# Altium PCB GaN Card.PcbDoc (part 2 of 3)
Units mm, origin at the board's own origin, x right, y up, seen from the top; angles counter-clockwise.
Board outline 50 x 40 mm, 6 copper layers (Top Layer, MidLayer1, MidLayer2, MidLayer3, MidLayer4, Bottom Layer), stack 1.981 mm thick; 88 components, 77 nets, 322 pads, 257 vias.
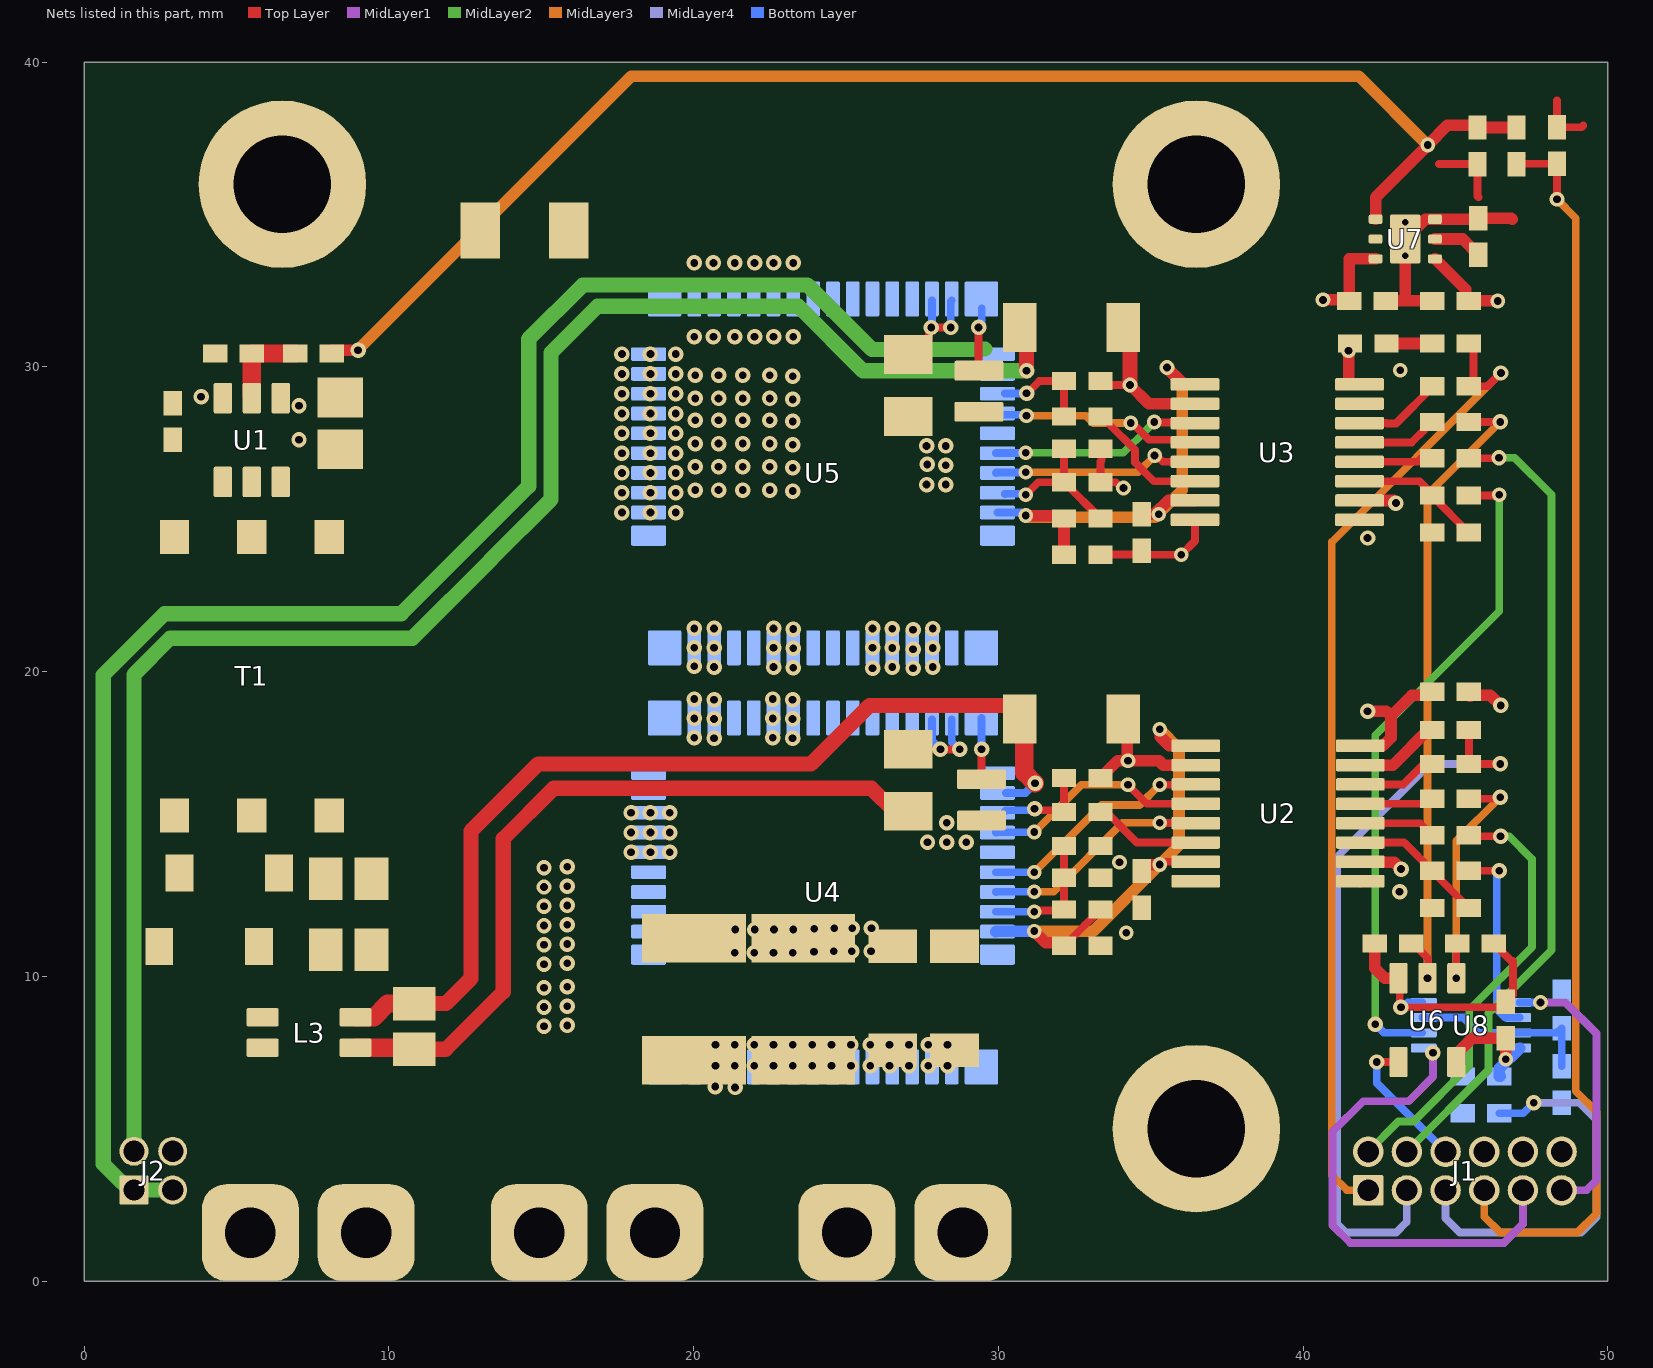
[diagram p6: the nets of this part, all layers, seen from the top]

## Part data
C1 C28 C30 C36 C37: library part CMP-0006356-2, "CAP, CERM, 0.1 uF, 50 V, +/- 10%, X7R, AEC-Q200 Grade 1, 0402", Cap_Case=0402, Manufacturer=MuRata, Supplier Part Number 1=490-10672-1-ND, TempCo=X7R, Tolerance_%=10%, Value1=Unknown, Value2=50V, ValueDisplayed=0.1uF
C2 C9 C10 C21: library part CMP-0076706-1, "CAP, CERM, 4.7 µF, 25 V,+/- 10%, X7R, AEC-Q200 Grade 1, 0805", Cap_Case=2x1.25x1.25mm, Manufacturer=TDK, Supplier Part Number 1=445-6967-1-ND, TempCo=X7R, Tolerance_%=10%, Value2=25V, ValueDisplayed=4.7µF
C3 C4 C13 C14 C16 C17: library part CMP-0006308-2, "CAP, CERM, 100 pF, 50 V, +/- 5%, C0G/NP0, AEC-Q200 Grade 1, 0402", Cap_Case=0402, Manufacturer=TDK, Supplier Part Number 1=445-5596-1-ND, TempCo=C0G/NP0, Tolerance_%=5%, Value1=Unknown, Value2=50V, ValueDisplayed=100pF
C5 C6 C7 C8 C39: library part CMP-0085818-1, "CAP, CERM, 1 µF, 10 V,+/- 10%, X7S, AEC-Q200 Grade 1, 0402", Cap_Case=0402, Manufacturer=MuRata, TempCo=X7S, Tolerance_%=10%, Value2=10V, ValueDisplayed=1µF
C11 C12: library part CMP-0008807-2, "CAP, CERM, 10 uF, 25 V, +/- 10%, X7S, AEC-Q200 Grade 1, 1206_190", Cap_Case=1206, Manufacturer=MuRata, Supplier Part Number 1=490-12661-1-ND, TempCo=X7S, Tolerance_%=10%, Value1=Unknown, Value2=25V, ValueDisplayed=10uF
C15 C19: library part CMP-0078265-1, "CAP, CERM, 0.22 µF, 16 V,+/- 10%, X7R, AEC-Q200 Grade 1, 0402", Cap_Case=0402, Manufacturer=MuRata, Supplier Part Number 1=490-10671-1-ND, TempCo=X7R, Tolerance_%=10%, Value2=16V, ValueDisplayed=0.22µF
C18 C20: library part CMP-0083622-1, "CAP, CERM, 2.2 µF, 25 V,+/- 10%, X7R, AEC-Q200 Grade 1, 0805", Cap_Case=0805, Manufacturer=MuRata, Supplier Part Number 1=490-4787-1-ND, TempCo=X7R, Tolerance_%=10%, Value2=25V, ValueDisplayed=2.2µF
C22 C23: library part CMP-0084048-1, "CAP, CERM, 0.022 µF, 1000 V,+/- 10%, X7R, AEC-Q200 Grade 1, 1206", Cap_Case=1206, Manufacturer=Kemet, TempCo=X7R, Tolerance_%=10%, Value2=1000V, ValueDisplayed=0.022µF
C24 C25: library part CMP-0009326-2, "CAP, CERM, 0.1 uF, 1000 V, +/- 10%, X7R, 1812", Cap_Case=1812, Manufacturer=Kemet, Supplier Part Number 1=399-6523-1-ND, TempCo=X7R, Tolerance_%=10%, Value1=Unknown, Value2=1000V, ValueDisplayed=0.1uF
C26 C27: library part CMP-0006356-1, "CAP, CERM, 0.1 uF, 50 V, +/- 10%, X7R, AEC-Q200 Grade 1, 0402", Cap_Case=0402, Manufacturer=MuRata, Supplier Part Number 1=490-10672-1-ND, TempCo=X7R, Tolerance_%=10%, Value1=Unknown, Value2=50V, ValueDisplayed=0.1uF
C32 C33 C34 C35: library part CMP-0860835-1, "CAP, CERM, 43 pF, 50 V,+/- 5%, C0G/NP0, AEC-Q200 Grade 1, 0402", Cap_Case=0402, Manufacturer=MuRata, TempCo=C0G/NP0, Tolerance_%=5%, Value2=50V, ValueDisplayed=43pF
C38: library part CMP-0006324-2, "CAP, CERM, 0.01 uF, 50 V, +/- 10%, X7R, AEC-Q200 Grade 1, 0402", Cap_Case=0402, Manufacturer=TDK, Supplier Part Number 1=445-6893-1-ND, TempCo=X7R, Tolerance_%=10%, Value1="0.333065 ohm", Value2=50V, ValueDisplayed=0.01uF
"CAUTION HOT SURFACE": library part CMP-0074837-1, "IEC 61010-1 Hot Surface Warning"
D2 D3: library part CMP-0028524-2, "Diode, Schottky, 20 V, 0.5 A, SOD-123", Manufacturer="ON Semiconductor", Value1=0.5A, Value2=0.385V
"DANGER HIGH VOLTAGE": library part CMP-0074835-1, "IEC 61010-1 High Voltage Warning"
J1: library part CMP-0120913-1, Current_A=3.4A, Digikey Part Number=SAM15643-ND, Manufacturer=Samtec, Mouser Part Number=200-FTSH10601LDRA, Operating Temperature Range="-55°C to +125°C"
J2: library part CMP-0120912-1, "Connector Unshrouded Header HDR 4 POS 1.27mm Solder RA Thru-Hole", Current_A=3.4A, Digikey Part Number=612-FTSH-102-01-L-D-RA-ND, Manufacturer=Samtec, Mouser Part Number=200-FTSH10201LDRA, Operating Temperature Range="-55°C to +125°C"
L1 L2: library part CMP-0089347-1, "4.7µH Unshielded Inductor 1.1A 426mOhm Max 0806 (2016 Metric)", Digikey Part Number=2037-SDEM20161T-4R7MSCT-ND, Manufacturer=Cyntec, Operating Temperature Range="-55°C to +125°C", Test Frequency=1MHz, Tolerance_%=20%
L3: library part CMP-0001686-1, "2 Line Common Mode Choke Surface Mount 1 kOhms @ 100 MHz 800mA DCR 150mOhm", Digikey Part Number=445-ACT32P-102-2P-TL01CT-ND, Impedance At Frequency="1000Ω @ 100MHz", Manufacturer=TDK, Mouser Part Number=810-ACT32P1022P-TL01, Operating Temperature Range="-55°C to +150°C", Tolerance_%=+30/-20%
LBL1: library part CMP-0003625-1, "Thermal Transfer Printable Labels, 0.650\" W x 0.200\" H - 10,000 per roll", Manufacturer=Brady, Supplier Part Number 1=97C5133
Logo1: library part CMP-0074844-1
Logo3: library part CMP-0074847-1, "FCC_disclaimer"
Logo4: library part CMP-0074769-1
R1 R2 R5 R6: library part CMP-0026404-2, "RES, 49.9, 1%, 0.063 W, AEC-Q200 Grade 0, 0402", Manufacturer=Vishay-Dale, Power_W=63mW, Supplier Part Number 1=541-49.9LCT-ND, TempCo="100 ppm/C", Tolerance_%=1%, Value2=0.063W, Value_Code=49R9, ValueDisplayed=49.9
R3 R4: library part CMP-0025951-3, "RES, 100, 1%, 0.063 W, AEC-Q200 Grade 0, 0402", Manufacturer=Vishay-Dale, Power_W=63mW, Supplier Part Number 1=541-100LCT-ND, TempCo="100 ppm/C", Tolerance_%=1%, Value2=0.063W, Value_Code=100R, ValueDisplayed=100
R7 R9: library part CMP-0025950-3, "RES, 100 k, 1%, 0.063 W, AEC-Q200 Grade 0, 0402", Manufacturer=Vishay-Dale, Power_W=63mW, Supplier Part Number 1=541-100KLCT-ND, TempCo="100 ppm/C", Tolerance_%=1%, Value2=0.063W, Value_Code=100k
R8 R14: library part CMP-0077124-1, "RES, 10.0 k, 0.1%, 0.1 W, AEC-Q200 Grade 0, 0402", Manufacturer=Vishay/Beyschlag, Power_W=100mW, Supplier Part Number 1=MCS0402-10.0K-MBCT-ND, TempCo="25 ppm/C", Tolerance_%=0.1%, Value2=0.1W, Value_Code=10k0, ValueDisplayed=10.0k
R10 R15: library part CMP-0026992-3, "RES, 0, 5%, 0.1 W, AEC-Q200 Grade 0, 0402", Manufacturer=Panasonic, Power_W=100mW, Supplier Part Number 1=P0.0JCT-ND, TempCo="600 ppm/C", Tolerance_%=5%, Value2=0.1W, Value_Code=0000, ValueDisplayed=0
R11 R12 R21 R22: library part CMP-0026902-3, "RES, 300, 5%, 0.063 W, AEC-Q200 Grade 0, 0402", Manufacturer=Vishay-Dale, Power_W=63mW, Supplier Part Number 1=541-300JCT-ND, TempCo="200 ppm/C", Tolerance_%=5%, Value2=0.063W, Value_Code=300R, ValueDisplayed=300
R13 R23: library part CMP-0026164-2, "RES, 20.0, 1%, 0.063 W, AEC-Q200 Grade 0, 0402", Manufacturer=Vishay-Dale, Power_W=63mW, Supplier Part Number 1=541-20.0LCT-ND, TempCo="100 ppm/C", Tolerance_%=1%, Value2=0.063W, Value_Code=20R0, ValueDisplayed=20.0
R16: library part CMP-0081856-1, "RES, 0, 0%, 0.2 W, AEC-Q200 Grade 0, 0402", Manufacturer=Vishay-Dale, Power_W=200mW, Supplier Part Number 1=541-0.0YBTR-ND, Tolerance_%=0%, Value2=0.2W, Value_Code=0
R25: library part CMP-0018573-3, "RES, 0, 5%, 0.25 W, AEC-Q200 Grade 0, 1206", Manufacturer=Vishay-Dale, Power_W=250mW, Supplier Part Number 1=541-0.0ECT-ND, TempCo="200 ppm/C", Tolerance_%=5%, Value2=0.25W, Value_Code=0000, ValueDisplayed=0
T1: library part CMP-0030718-1, "Transformer, 475uH, SMT", Manufacturer="Wurth Elektronik", Supplier Part Number 1=732-4458-1-ND, ValueDisplayed=475uH
TH1 TH2 TH3: library part CMP-0003719-1, "Testpoint", Manufacturer="Texas Instruments", PartNumber=TP_H0.45P0.75
TP1 TP2 TP3 TP4 TP5 TP6: library part CMP-0082316-1, "PCB Pin, 0.04\" DIA, Edge-Mount", Manufacturer=Mill-Max, Supplier Part Number 1=575-3621032150000
U1: library part CMP-0860735-1, "SN6505DQDBVRQ1, DBV0006A (SOT-23-6)", Alternate Manufacturer="Texas Instruments", Alternate PartNumber=SN6505DQDBVTQ1
U2 U3: library part CMP-0090469-1, "General Purpose Digital Isolator 2500Vrms 4 Channel 100Mbps 85kV/µs CMTI 16-SSOP (0.154\", 3.90mm Width)", Digikey Part Number=296-51207-1-ND, Manufacturer="Texas Instruments", Max Supply Voltage=5.5V, Min Supply Voltage=2.25V, Mouser Part Number=595-ISO7741FQDBQRQ1, Nominal Supply Current=1.5-18mA, Operating Temperature Range="-40°C to +125°C"
U4 U5: library part CMP-0094891-1, "650-V 30-mΩ GaN FET with Integrated Driver, Protection, and Temperature Reporting", Manufacturer="Texas Instruments", Max Supply Voltage=18V, Min Supply Voltage=7.5V, Nominal Supply Current=16mA, Operating Temperature Range="-40°C to +150°C", Output Voltage=520V
U6: library part CMP-0051573-2, "Automotive Catalog Single 2-Input Positive-AND Gate, DBV0005A (SOT-23-5)", F @ Nom Voltage(Max)(Mhz)=75, Generic Part Number=SN74AHC1G08-Q1, ICC @ Nom Voltage(Max)(mA)=0.01, Manufacturer="Texas Instruments", Operating Temperature Range="-40 to 125 C", Rating=Automotive, tpd @ Nom Voltage(Max)(ns)=12.3,7.9, Voltage(Nom)(V)=3.3,5
U7: library part CMP-0082417-1, "Low Noise, High-Bandwidth PSRR Low-Dropout 150mA Linear Regulator for Automotive Applications, DRV0006A (WSON-6)", Alternate Manufacturer="Texas Instruments", Operating Temperature Range="-40 to 125 C", Rating=Automotive
U8: library part CMP-0121233-1, "Automotive Dual Bilateral Analog Switch", Digikey Part Number=296-29056-1-ND, Manufacturer="Texas Instruments", Max Supply Voltage=5.5V, Min Supply Voltage=1.65V, Mouser Part Number=595-74LVC2G66QDCURQ1, Nominal Supply Current=1-15uA, On State Resistance=6Ω, Operating Temperature Range="-40°C to +125°C"

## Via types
v1: diameter 0.508, hole 0.254, Top Layer to Bottom Layer, tented both sides, 218 vias
v2: diameter 0.483, hole 0.254, Top Layer to Bottom Layer, tented both sides, 35 vias
v3: diameter 0.508, hole 0.254, Top Layer to Bottom Layer, 2 vias
v4: diameter 0.5, hole 0.2, Top Layer to Bottom Layer, 2 vias

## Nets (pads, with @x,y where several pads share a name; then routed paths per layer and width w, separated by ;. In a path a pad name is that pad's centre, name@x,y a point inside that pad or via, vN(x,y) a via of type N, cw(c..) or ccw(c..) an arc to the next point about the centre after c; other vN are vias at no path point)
3V3: C5.1 C6.1 C28.1 C36.1 C39.1 U2.10 U2.16 U3.10 U3.16 U6.5 U7.1 U8.8 | length 14.9
  Top Layer w0.381: v2(41.492,30.534) 41.502,30.534 41.502,29.444 41.517,29.429 U3.16@41.856,29.429 ; U3.10@41.856,25.619 42.968,25.619 v1(43.052,25.535) ; U2.16@41.881,17.567 42.623,17.567 42.889,17.834 42.889,18.545 ; v1(42.118,18.698) 42.737,18.698 42.889,18.545 ; U2.10@42.246,13.743 42.996,13.743 v1(43.22,13.519) ; C6.1@44.245,19.231 43.575,19.231 42.889,18.545 ; U7.1@44.332,33.55 45.333,32.549 45.333,32.169 v2(46.395,32.169) ; U6.5@45.033,7.188 45.033,7.444 45.553,7.963 C36.1@46.659,7.963 46.657,7.961 46.657,7.282 v2(46.655,7.28)
  Bottom Layer w0.381: C28.1@46.476,6.715 C28.1@46.445,6.715 46.445,6.975 U8.8@47.115,7.645
5V0: C1.1 C2.1 C37.1 J1.12 T1.5 U1.2 U7.6 | length 3.1
  Top Layer w0.381: v2(40.656,32.203) 41.484,32.203 C37.1@41.518,32.169 41.518,33.55 U7.6@42.382,33.55
  other v1: 7.046,27.615
5V_H: C8.1 C15.2 R15.1 U2.1 U2.7 U4.51 | length 17.5
  Top Layer w0.254: C15.2@32.155,11.103 32.26,11.103 32.839,11.683 32.842,11.683 R15.1@33.355,12.195 ; v2(35.295,13.669) 35.384,13.757 U2.7@36.481,13.757
  Top Layer w0.381: v2(31.18,11.484) 31.561,11.103 C15.2@32.155,11.103 ; C8.1@34.711,13.456 34.923,13.669 v2(35.295,13.669) ; v2(35.295,18.114) 35.314,18.094 35.314,17.858 35.605,17.567 U2.1@36.481,17.567
  MidLayer3 w0.381: v2(31.18,11.484) 33.11,11.484 v2(35.295,13.669) 35.93,14.304 35.93,17.479 v2(35.295,18.114)
  Bottom Layer w0.381: U4.51@29.921,11.469 29.928,11.477 31.173,11.477 v2(31.18,11.484)
5V_L: C7.2 C19.2 R10.1 U3.1 U3.7 U5.51 | length 16.3
  Top Layer w0.381: v2(30.901,25.124) 32.058,25.124 R10.1@32.155,25.027 C19.2@32.155,23.842 ; C7.2@34.711,25.165 v2@35.121,25.165 ; v2@35.263,25.193 v2(35.263,25.165) v2@35.121,25.165 ; v2(35.533,29.98) 36.084,29.429 U3.1@36.456,29.429 ; U3.7@36.456,25.619 35.575,25.619 v2@35.121,25.165
  MidLayer3 w0.381: v2(30.901,25.124) 30.928,25.124 30.979,25.073 35.143,25.073 v2@35.235,25.165 ; v2(35.263,25.165) v2@35.235,25.165 ; v2(35.533,29.98) 36.031,29.482 36.031,25.961 v2@35.235,25.165
  Bottom Layer w0.254: U5.51@29.971,25.223 v2@30.74,25.223
DGND: C1.2 C2.2 C3.2 C4.2 C5.2 C6.2 C26.2 C27.2 C28.2 C30.2 C32.2 C33.2 C34.2 C35.2 C36.2 C37.2 C38.2 C39.2 J1.8 J1.10 R8.1 R14.1 U1.4 U1.6 U2.9 U2.15 U3.9 U3.15 U6.3 U7.3 U7.7@43.357,34.2 U8.4 | length 25.7
  Top Layer w0.254: U6.3@43.133,9.648 43.175,9.607 43.175,9.029 v1(43.216,8.987) 46.486,8.987 46.659,9.16 C36.2@46.659,9.163 46.892,9.396 46.892,10.504 46.832,10.504 C34.2@46.258,11.078 ; C35.2@44.245,18.088 C35.2@44.302,18.088 ; 44.464,36.66 C27.2@45.727,36.66 45.727,35.603 45.757,35.573 ; 48.335,38.75 R14.1@48.335,37.87 49.141,37.87 49.2,37.929
  Top Layer w0.381: U2.9@41.881,13.122 U2.9@41.896,13.108 ; U2.15@41.881,16.932 42.952,16.932 44.108,18.088 C35.2@44.245,18.088 ; C33.2@42.352,11.078 42.352,10.267 42.681,9.938 U6.3@43.133,9.938 U6.3@43.133,9.648 ; C37.2@42.718,32.169 43.425,32.169 ; C5.2@42.742,30.772 C32.2@44.133,30.772 ; v1(43.17,12.778) v1@43.213,12.778 ; v4(43.357,33.65) 43.357,32.237 43.425,32.169 ; U7.7@43.357,34.2 44.007,34.85 U7.3@44.332,34.85 45.722,34.85 C38.2@45.757,34.884 46.834,34.884 46.868,34.85 ; C39.2@44.133,32.169 43.425,32.169 ; C6.2@45.48,19.196 45.515,19.231 46.148,19.231 v1(46.489,18.891)
  Bottom Layer w0.254: v1@43.297,8.905 43.297,8.999 43.442,9.145 U8.4@43.915,9.145
  other v1: 42.118,24.387
  other v2: 43.194,29.893
  other v3: 7.046,28.731 3.833,29.024
  other v4: 43.357,34.75
EN: C30.1 R16.2 U1.5 | length 2.8
  Top Layer w0.6: U1.5@5.496,29.078 C30.1@5.496,30.445 ; C30.1@5.501,30.446 R16.2@6.926,30.446
EN_DRV: J1.5 R3.1 R8.2 | length 13.9
  MidLayer4 w0.254: J1.5@44.679,2.975 44.679,2.061 45.149,1.591 49.124,1.591 49.632,2.098 49.632,5.3 49.077,5.854 v1(47.574,5.854)
  Bottom Layer w0.254: R8.2@46.445,5.505 47.225,5.505 v1(47.574,5.854) R3.1@48.489,5.854
"EN_ISO 12V": J1.7 R4.1 R14.2 | length 41.7
  Top Layer w0.254: R4.1@47.178,36.933 47.005,36.76 R4.1@47.005,36.66 47.015,36.67 R14.2@48.335,36.67 v2(48.335,35.505)
  MidLayer3 w0.254: J1.7@45.949,2.975 45.949,2.113 46.471,1.591 49.009,1.591 49.632,2.213 49.632,5.554 48.954,6.232 48.954,34.886 v2(48.335,35.505)
GaN_FAULT: J1.6 U6.4 | length 4.6
  Top Layer w0.254: v1(42.424,7.188) U6.4@43.133,7.188
  Bottom Layer w0.254: v1(42.424,7.188) 42.424,6.5 J1.6@44.679,4.245
HS_FAULT: C34.1 R22.2 U6.1 | length 8.7
  Top Layer w0.254: v1(45.033,9.938) 45.033,11.053 C34.1@45.058,11.078 ; R22.2@45.445,15.828 46.42,15.828 v1(46.471,15.878)
  MidLayer3 w0.254: v1(45.033,9.938) 45.033,14.441 v1(46.471,15.878)
HS_OC: C35.1 J1.3 R23.2 | length 24.4
  Top Layer w0.254: C35.1@45.445,18.088 R23.2@45.445,16.971 v1(46.471,16.971)
  MidLayer4 w0.254: J1.3@43.409,2.975 43.409,1.939 43.061,1.591 41.404,1.591 41.12,1.875 41.12,13.928 44.162,16.971 v1(46.471,16.971)
HS_PWM: J1.11 U8.5 | length 9
  MidLayer1 w0.254: v2(47.795,9.139) 48.615,9.139 49.632,8.122 49.632,3.304 49.303,2.975 J1.11@48.489,2.975
  MidLayer3 w0.254: v2@47.789,9.132 v2(47.795,9.139)
  Bottom Layer w0.254: U8.5@47.115,9.145 47.118,9.142 47.792,9.142 v2(47.795,9.139)
HS_PWM_IN: R2.1 U8.6 | length 6.4
  Top Layer w0.254: R2.1@45.445,13.465 v1(46.445,13.465)
  Bottom Layer w0.254: v1(46.445,13.465) 46.445,13.397 46.358,13.31 46.358,8.925 46.639,8.645 U8.6@47.115,8.645
HS_TEMP: J1.2 R21.2 | length 14.5
  Top Layer w0.254: R21.2@45.445,14.634 45.482,14.597 v1(46.486,14.597)
  MidLayer2 w0.254: J1.2@42.139,4.245 43.129,5.235 43.629,5.235 45.459,7.065 45.459,8.904 47.514,10.959 47.514,13.848 46.765,14.597 v1(46.486,14.597)
HVBUS: C22.1 C23.1 C24.1 C25.1 TP1.1 TP4.1 U4.2 U4.3 U4.4 U4.5 U4.6 U4.7 U4.8 U4.9 U4.10 U4.11 U4.12 U4.13 U4.14 U4.15
  other v1: 21.358,6.354 20.712,6.382 20.715,7.065 21.35,7.065 21.985,7.065 22.62,7.065 23.255,7.065 23.89,7.065 24.525,7.065 25.16,7.065 25.795,7.065 26.43,7.065 27.065,7.065 27.7,7.065 28.335,7.065 20.715,7.75 21.35,7.75 21.985,7.75 22.62,7.75 23.255,7.75 23.89,7.75 24.525,7.75 25.16,7.75 25.795,7.75 26.43,7.75 27.065,7.75 27.7,7.75 28.335,7.75
ISO_12V_H: C12.1 C21.1 L3.2 U4.44 | length 32.5
  Top Layer w0.5: C21.1@10.825,9.106 11.868,9.106 12.695,9.933 12.695,14.77 14.896,16.971 23.85,16.971 25.77,18.891 30.4,18.891 30.7,18.591 C12.1@30.7,18.45
  Top Layer w0.6: L3.2@8.901,8.656 9.506,8.656 9.956,9.106 C21.1@10.825,9.106 ; C12.1@30.7,18.45 30.855,18.295 30.855,16.686 v1(31.205,16.336)
  Bottom Layer w0.254: U4.44@30.252,16.019 30.889,16.019 v1(31.205,16.336)
ISO_12V_L: C11.1 J2.2 U5.44 | length 56.2
  Top Layer w0.5: C11.1@30.7,31.3 30.925,31.075 30.925,29.875 v1(30.926,29.874)
  MidLayer2 w0.5: J2.2@1.63,4.258 1.63,19.909 2.821,21.1 10.769,21.1 13.34,23.671 13.34,23.676 15.319,25.655 15.319,30.469 16.844,31.994 23.441,31.994 25.561,29.874 v1(30.926,29.874)
  Bottom Layer w0.254: U5.44@29.921,29.773 U5.44@29.971,29.773 30.757,29.773 30.857,29.874 v1(30.926,29.874)
ISO_-4V_L: J2.4
LS_FAULT: C33.1 R12.2 U6.2 | length 21.5
  Top Layer w0.254: C33.1@43.635,11.052 44.113,10.575 44.113,9.968 v1(44.083,9.938) ; R12.2@45.593,28.197 v1(46.471,28.197)
  MidLayer3 w0.254: v1(44.083,9.938) 44.083,25.81 v1(46.471,28.197)
LS_OC: C32.1 J1.1 R13.2 | length 32.6
  Top Layer w0.254: C32.1@45.333,30.772 45.593,30.513 45.593,29.366 46.069,29.366 46.069,29.376 v1(46.496,29.803)
  MidLayer3 w0.254: J1.1@42.139,2.975 41.446,2.975 40.946,3.475 40.946,24.253 v1(46.496,29.803)
LS_PWM: J1.9 U8.1 | length 15.8
  MidLayer1 w0.254: v1(44.265,7.495) 44.265,6.702 43.466,5.904 41.981,5.904 40.97,4.893 40.97,1.83 41.55,1.25 46.598,1.25 47.219,1.871 J1.9@47.219,2.975
LS_PWM_IN: R1.1 U8.2 | length 21.6
  Top Layer w0.254: R1.1@45.593,25.784 46.42,25.784 v2(46.445,25.81)
  MidLayer2 w0.254: v1(42.374,8.43) 42.374,17.909 46.445,21.981 v2(46.445,25.81)
  Bottom Layer w0.254: v1(42.374,8.43) 42.659,8.145 U8.2@43.915,8.145
LS_TEMP: J1.4 R11.2 | length 26.6
  Top Layer w0.254: R11.2@45.593,27.004 46.412,27.004 v1(46.433,27.024)
  MidLayer2 w0.254: J1.4@43.409,4.245 46.088,6.924 46.088,8.792 48.16,10.863 48.16,25.805 46.94,27.024 v1(46.433,27.024)
NC1: R25.2 TH1.1
NC2: TH2.1
NC3: TH3.1
NCT1: T1.2
NCU7: U7.5
NCU51: U4.1
NCU61: U5.1
NCU516: U4.16
NCU517: U4.17
NCU527: U4.27
NCU543: U4.43
NCU547: U4.47
NCU552: U4.52
NCU616: U5.16
NCU617: U5.17
NCU627: U5.27
NCU643: U5.43
NCU647: U5.47
NCU652: U5.52
NetC3_1: C3.1 R1.2 U3.11 | length 5
  Top Layer w0.254: U3.11@41.856,26.254 43.823,26.254 44.293,25.784 44.345,25.784 44.518,25.611 R1.2@44.518,25.559 ; R1.2@44.245,25.784 44.245,25.765 C3.1@45.445,24.565 45.345,24.565 C3.1@45.172,24.738
NetC4_1: C4.1 R2.2 U2.11 | length 4.5
  Top Layer w0.254: U2.11@41.881,14.392 43.318,14.392 R2.2@44.245,13.465 44.245,13.446 C4.1@45.445,12.246
NetC9_1: C9.1 D2.1 L3.3
NetC9_2: C9.2 C10.1 T1.3
NetC10_2: C10.2 D3.2 L3.4
NetC13_2: C13.2 R5.1 U4.45 | length 3
  Top Layer w0.254: v1(31.188,15.497) 31.236,15.449 32.102,15.449 R5.1@32.129,15.421 ; R5.1@32.155,15.447 C13.2@32.155,16.488
  Bottom Layer w0.254: U4.45@30.215,15.421 30.243,15.449 31.139,15.449 v1(31.188,15.497)
NetC14_2: C14.2 R7.2 R10.2 U5.50 | length 5.1
  Top Layer w0.254: v2@30.963,25.81 v2(30.901,25.81) 31.312,26.221 C14.2@32.155,26.221 ; R7.2@32.155,27.32 C14.2@32.155,26.221 ; R10.2@33.255,25.027 R10.2@33.355,25.027 32.161,26.221 C14.2@32.155,26.221
  Bottom Layer w0.254: U5.50@30.215,25.835 30.221,25.841 30.869,25.841 v2(30.901,25.81)
NetC16_2: C16.2 R6.2 U5.45 | length 3.3
  Top Layer w0.254: v1(30.926,29.137) 30.944,29.137 31.345,29.538 C16.2@32.155,29.538 R6.2@32.155,28.375
  Bottom Layer w0.254: U5.45@30.215,29.137 30.222,29.13 30.919,29.13 v1(30.926,29.137)
NetC17_2: C17.2 R9.2 R15.2 U4.50 | length 4.3
  Top Layer w0.254: v2(31.18,12.119) 31.218,12.157 32.117,12.157 R15.2@32.155,12.195 C17.2@32.155,13.237 R9.2@32.155,14.278
  Bottom Layer w0.254: U4.50@29.921,12.119 v2(31.18,12.119)
NetC18_1: C18.1 U4.40 U4.41 | length 4.2
  Top Layer w0.254: C18.1@26.686,17.45 v1(28.1,17.45) 28.108,17.442 28.722,17.442 v1@28.73,17.434
  Bottom Layer w0.254: U4.40@27.821,18.429 27.821,17.729 v1(28.1,17.45) ; U4.41@28.471,18.429 28.471,17.693 v1@28.73,17.434
  other v1: 28.73,17.45
NetC20_1: C20.1 U5.40 U5.41 | length 3.8
  Top Layer w0.254: C20.1@27.04,30.407 27.205,30.407 27.713,30.915 27.713,31.138 27.802,31.227 v1(27.802,31.296) v1@28.31,31.296 ; v1@28.437,31.169 v1@28.31,31.296 ; v1(28.437,31.296) v1@28.31,31.296
  Bottom Layer w0.254: v1(27.802,31.296) 27.821,31.315 U5.40@27.821,32.183 ; v1@28.437,31.423 28.437,32.149 U5.41@28.471,32.183
NetC26_1: C26.1 R3.2 U8.3 U8.7 | length 6.1
  Bottom Layer w0.254: U8.3@43.915,8.645 45.265,8.645 45.765,8.145 47.115,8.145 48.335,8.145 C26.1@48.489,8.299 R3.2@48.489,7.054
NetC27_1: C27.1 R4.2 R16.1 U7.4 | length 47
  Top Layer w0.381: R16.1@8.126,30.546 v1(8.985,30.546) ; U7.4@42.382,34.85 42.382,35.573 v2(44.093,37.283) 44.739,37.929 45.657,37.929 C27.1@45.727,37.86 R4.2@47.005,37.86
  MidLayer3 w0.381: v1(8.985,30.546) 8.985,30.57 17.956,39.54 41.836,39.54 v2(44.093,37.283)
NetC38_1: C38.1 U7.2 | length 1.6
  Top Layer w0.381: U7.2@44.332,34.2 45.241,34.2 C38.1@45.757,33.684
NetD2_2: D2.2 D3.1 T1.1
NetL1_2: L1.2 U4.42 | length 2
  Top Layer w0.254: L1.2@29.445,16.469 29.45,16.474 v1(29.45,17.45)
  Bottom Layer w0.254: U4.42@29.446,18.479 29.45,18.475 v1(29.45,17.45)
NetL2_2: L2.2 U5.42 | length 2.1
  Top Layer w0.254: v1(29.35,31.3) 29.35,29.892 L2.2@29.362,29.88
  Bottom Layer w0.254: v1(29.35,31.3) 29.35,31.369 29.453,31.472 U5.42@29.453,31.931
NetR5_2: R5.2 U2.6 | length 3.5
  Top Layer w0.254: R5.2@33.423,15.515 34.546,14.392 U2.6@36.481,14.392
NetR6_1: R6.1 U3.6 | length 4.3
  Top Layer w0.254: R6.1@33.355,28.375 33.455,28.375 33.628,28.202 33.628,28.142 34.485,27.285 34.485,26.869 35.1,26.254 U3.6@36.456,26.254
NetR11_1: R11.1 U3.12 | length 2.6
  Top Layer w0.254: U3.12@41.856,26.889 43.774,26.889 43.888,27.004 44.387,27.004 44.393,27.01 R11.1@44.393,27.004
NetR12_1: R12.1 U3.13 | length 2.7
  Top Layer w0.254: U3.13@41.856,27.524 43.572,27.524 43.972,27.924 43.972,28.024 44.145,28.197 R12.1@44.245,28.197
NetR13_1: R13.1 U3.14 | length 3
  Top Layer w0.254: U3.14@41.856,28.159 42.736,28.159 42.749,28.147 43.052,28.147 44.271,29.366 R13.1@44.393,29.366
NetR21_1: R21.1 U2.12 | length 2.5
  Top Layer w0.254: U2.12@41.881,15.027 43.852,15.027 R21.1@44.245,14.634
NetR22_1: R22.1 U2.13 | length 2.4
  Top Layer w0.254: U2.13@41.881,15.662 44.08,15.662 R22.1@44.245,15.828
NetR23_1: R23.1 U2.14 | length 2.6
  Top Layer w0.254: U2.14@41.881,16.297 43.294,16.297 43.906,16.91 44.185,16.91 R23.1@44.245,16.971
NetT1_4: T1.4 U1.3
NetT1_6: T1.6 U1.1
NetU2_3: U2.3 U4.48 | length 7.8
  Top Layer w0.254: v2(35.295,16.285) 35.301,16.291 36.475,16.291 U2.3@36.481,16.297
  MidLayer3 w0.254: v2(31.18,13.415) 33.39,15.624 34.634,15.624 v2(35.295,16.285)
  Bottom Layer w0.254: U4.48@29.921,13.419 29.923,13.417 31.178,13.417 v2(31.18,13.415)
NetU2_4: U2.4 U4.46 | length 7.5
  Top Layer w0.254: v2(34.253,16.285) 34.876,15.662 U2.4@36.481,15.662
  MidLayer3 w0.254: v2(31.18,14.735) 32.729,16.285 v2(34.253,16.285)
  Bottom Layer w0.254: U4.46@29.921,14.719 29.929,14.727 31.172,14.727 v2(31.18,14.735)
NetU2_5: U2.5 U4.49 | length 7.5
  Top Layer w0.254: v2(35.295,15.04) 35.301,15.034 36.475,15.034 U2.5@36.481,15.027
  MidLayer3 w0.254: v2(31.18,12.78) 31.815,12.78 34.076,15.04 v2(35.295,15.04)
  Bottom Layer w0.254: U4.49@29.921,12.769 29.926,12.774 31.175,12.774 v2(31.18,12.78)
NetU3_3: U3.3 U5.48 | length 7
  Top Layer w0.254: v2(35.117,28.197) 35.136,28.178 36.437,28.178 U3.3@36.456,28.159
  MidLayer2 w0.254: v2(30.901,27.181) 34.104,27.181 34.869,27.946 34.869,27.95 v2(35.117,28.197)
  Bottom Layer w0.254: U5.48@29.921,27.173 29.925,27.177 30.897,27.177 v2(30.901,27.181)
NetU3_4: U3.4 U5.46 | length 6.9
  Top Layer w0.254: v2(34.349,28.162) 34.398,28.162 34.947,27.613 36.367,27.613 U3.4@36.456,27.524
  MidLayer3 w0.254: v2(30.926,28.401) 32.876,28.401 33.115,28.162 v2(34.349,28.162)
  Bottom Layer w0.254: U5.46@29.921,28.473 29.957,28.437 30.89,28.437 v2(30.926,28.401)
NetU3_5: U3.5 U5.49 | length 6.9
  Top Layer w0.254: v2(35.13,27.092) 35.191,27.092 35.395,26.889 U3.5@36.456,26.889
  MidLayer3 w0.254: v2(30.901,26.546) 34.584,26.546 v2(35.13,27.092)
  Bottom Layer w0.254: U5.49@29.921,26.523 29.932,26.535 30.889,26.535 v2(30.901,26.546)
PGND: C7.1 C11.2 C14.1 C16.1 C19.1 C20.2 C22.2 C23.2 C24.2 C25.2 J2.1 J2.3 L2.1 R7.1 R25.1 TP2.1 TP5.1 U3.2 U3.8 U5.18 U5.19 U5.20 U5.21 U5.22 U5.23 U5.24 U5.25 U5.26 U5.28 U5.29 U5.30 U5.31 U5.32 U5.33 U5.34 U5.35 U5.36 U5.37 U5.38 U5.39 | length 67.4
  Top Layer w0.254: C19.1@33.355,23.842 34.395,23.842 ; R7.1@33.355,27.32 33.39,27.285 33.39,26.937 33.355,26.902 33.355,26.221 33.851,26.221 34.046,26.026 v2(34.105,26.026) ; C16.1@33.355,29.417 33.362,29.41 v2(34.323,29.41) ; C7.1@34.914,23.838 v2(36.006,23.838) 36.456,24.288 U3.8@36.456,24.984
  Top Layer w0.381: v2(34.323,29.41) 34.939,28.794 U3.2@36.456,28.794
  Top Layer w0.5: C11.2@34.1,31.3 34.323,31.077 v2(34.323,29.41)
  MidLayer2 w0.5: J2.3@2.9,2.988 J2.1@1.63,2.988 1.501,2.988 1.241,3.248 1.212,3.248 0.62,3.84 0.62,19.889 2.631,21.9 10.4,21.9 14.585,26.085 14.585,30.917 16.363,32.694 23.731,32.694 25.851,30.574 29.276,30.574 29.294,30.592 29.562,30.592
  other v1: 21.35,10.778 21.985,10.778 22.62,10.778 23.255,10.778 23.946,10.803 24.596,10.822 25.186,10.824 25.821,10.824 21.366,11.535 22.001,11.535 22.636,11.535 23.271,11.535 23.962,11.56 24.612,11.579 25.201,11.581 25.836,11.581 17.646,25.223 18.581,25.223 19.414,25.223 17.646,25.873 18.581,25.873 19.414,25.873 23.251,25.928 20.055,25.962 20.817,25.962 21.615,25.962 22.494,25.962 27.643,26.14 28.278,26.14 17.646,26.523 18.581,26.523 19.414,26.523 23.251,26.69 20.055,26.724 20.817,26.724 21.615,26.724 22.494,26.724 28.278,26.775 27.669,26.8 17.646,27.173 18.581,27.173 19.414,27.173 27.643,27.41 28.278,27.41 23.251,27.452 20.055,27.486 20.817,27.486 21.615,27.486 22.494,27.486 17.646,27.823 18.581,27.823 19.414,27.823 23.251,28.214 20.055,28.248 20.817,28.248 21.615,28.248 22.494,28.248 17.646,28.473 18.581,28.473 19.414,28.473 23.251,28.935 20.055,28.969 20.817,28.969 21.615,28.969 22.494,28.969 17.646,29.123 18.581,29.123 19.414,29.123 23.251,29.697 20.055,29.731 20.817,29.731 21.615,29.731 22.494,29.731 17.646,29.773 18.581,29.773 19.414,29.773 17.646,30.423 18.581,30.423 19.414,30.423 20.021,30.993 20.65,30.993 21.35,30.993 22,30.993 22.621,30.993 23.271,30.993 20.021,33.414 20.65,33.414 21.35,33.414 22,33.414 22.621,33.414 23.271,33.414
SW: C8.2 C12.2 C13.1 C15.1 C17.1 C18.2 C21.2 L1.1 L3.1 R9.1 TP3.1 TP6.1 U2.2 U2.8 U4.18 U4.19 U4.20 U4.21 U4.22 U4.23 U4.24 U4.25 U4.26 U4.28 U4.29 U4.30 U4.31 U4.32 U4.33 U4.34 U4.35 U4.36 U4.37 U4.38 U4.39 U5.2 U5.3 U5.4 U5.5 U5.6 U5.7 U5.8 U5.9 U5.10 U5.11 U5.12 U5.13 U5.14 U5.15 | length 29.4
  Top Layer w0.381: C13.1@33.355,16.513 33.914,17.072 v2(34.253,17.072) ; C12.2@34.1,18.45 34.234,18.316 34.234,17.092 v2(34.253,17.072) ; U2.2@36.481,16.932 35.418,16.932 35.279,17.072 v2(34.253,17.072)
  Top Layer w0.5: C21.2@10.825,7.606 11.862,7.606 13.75,9.493 13.75,14.516 15.405,16.171 25.833,16.171 C18.2@26.583,15.421
  Top Layer w0.6: L3.1@8.901,7.656 10.775,7.656 C21.2@10.825,7.606
  other v1: 15.087,8.36 15.85,8.388 15.087,8.993 15.85,9.021 15.087,9.628 15.85,9.656 15.087,10.399 15.85,10.427 15.087,11.033 15.85,11.06 15.087,11.668 15.85,11.695 15.087,12.299 15.85,12.326 15.087,12.932 15.85,12.96 15.087,13.567 15.85,13.595 17.946,14.069 18.581,14.069 19.214,14.069 27.675,14.405 28.31,14.405 28.95,14.4 17.946,14.719 18.581,14.719 19.214,14.719 28.31,15.04 17.946,15.369 18.581,15.369 19.214,15.369 20.671,17.814 23.245,17.814 20.021,17.832 22.595,17.832 20.671,18.447 23.245,18.447 20.021,18.465 22.595,18.465 20.671,19.082 23.245,19.082 20.021,19.1 22.595,19.1 23.271,20.132 25.871,20.112 27.2,20.112 20.671,20.15 22.621,20.15 26.521,20.15 27.85,20.15 20.021,20.179 27.2,20.739 23.271,20.765 20.021,20.783 20.671,20.783 22.621,20.783 25.871,20.783 26.521,20.777 27.846,20.779 27.2,21.374 23.271,21.4 20.021,21.418 20.671,21.418 22.621,21.418 25.871,21.418 26.521,21.412 27.846,21.414
  other v2: 34.203,11.433 33.974,13.745
pads on no net: LBL1.0 U7.7@43.357,33.75 U7.7@43.357,34.65

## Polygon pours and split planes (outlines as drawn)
DGND on Bottom Layer "MidLayer4-DGND" (solid, remove dead copper, pour order 538): 40.4,31.931 40.4,39.2 40.9,39.7 49.2,39.7 50,38.9 50,0.5 40.4,0.5
PGND on Bottom Layer "BOTTOM_LAYER_PGND_P517" (solid, pour order 517): 3.31,5.189 3.86,4.639 3.86,2.365 3.31,1.783 3.31,0 10.177,0 10.64,0.463 10.64,17.244 17.783,24.387 27.935,24.387 28.681,25.134 28.681,33.214 28.101,33.795 16.245,33.795 14.35,31.9 14.35,27.915 3.31,16.874
SW on Bottom Layer "Bottom Layer-SW" (solid, pour order 516): 18.203,22.25 12.5,16.547 12.5,13.63 12.5,0 19.857,0 20.32,0.463 20.32,3.144 20.377,3.201 17.802,5.776 17.802,10.247 19.95,12.395 20.309,12.754 26.786,12.754 26.786,11.451 27.219,11.017 28.489,11.017 28.945,11.474 28.945,16.945 27.167,16.945 27.167,17.707 31.104,17.707 31.358,17.961 31.358,21.263 30.371,22.25
PGND on Bottom Layer "BOTTOM_LAYER_PGND_P501" (solid, pour order 501): 21.194,10.428 21.096,10.526 21.096,11.6 21.321,11.825 21.352,11.794 25.929,11.794 26.096,11.628 26.096,10.504 26.02,10.428
HVBUS on Bottom Layer "MidLayer4-PGND" (solid, pour order 473): 19.796,8.066 19.921,8.19 20.603,8.182 30.285,8.182 30.725,7.742 30.725,0 24.381,0 19.796,4.585
DGND on Top Layer "MidLayer4-DGND" (solid, remove dead copper, pour order 540): 41.629,39.05 42.279,39.7 49.2,39.7 50,38.9 50,1.615 48.885,0.5 42.414,0.5 41.629,1.284
5V0 on Top Layer "TOP_LAYER_5V0_P492" (solid, pour order 492): 9.15,27.974 9.368,27.756 9.368,26.749 9.076,26.457 7.859,26.457 7.193,27.123 6.142,27.123 5.796,26.777 5.796,25.885 5.979,25.702 5.979,23.802 5.014,23.802 5.014,25.696 5.196,25.879 5.196,26.777 5.198,26.779 5.198,26.813 4.901,27.123 3.469,27.123 3.243,26.897 3.243,26.848 2.385,26.848 2.201,27.032 2.201,27.749 2.194,27.756 2.412,27.974
DGND on Top Layer "TOP_LAYER_DGND_P498" (solid, pour order 498): 9.209,30.025 9.4,29.835 9.4,28.518 9.15,28.268 6.411,28.268 6.146,28.532 6.146,29.557 5.887,29.815 5.152,29.815 4.863,29.527 4.846,29.527 4.846,28.503 4.611,28.268 2.746,28.268 2.435,28.579 2.435,29.791 2.669,30.025 3.682,30.025 3.901,30.244 3.901,30.546 4.718,30.546 4.718,30.025
NetT1_6 on Top Layer "TOP_LAYER_NETT1_6_P491" (solid, pour order 491): 4.857,26.788 4.811,26.833 4.281,26.833 2.474,25.026 2.474,23.802 3.439,23.802 3.439,24.45 4.857,25.868
NetC9_2 on Top Layer "Top Layer-NetC9_2" (solid, pour order 542): 8.876,10.175 9.976,10.175 10.125,10.324 10.125,15.471 9.759,15.837 8.69,15.837 7.557,15.837 7.557,14.719 8.701,14.719 8.876,14.544
PGND on Top Layer "Top Layer-PGND 1" (solid, pour order 384): 26.252,29.023 26.252,26.678 27.1,25.831 28.686,25.831 29.58,26.724 30.088,27.232 32.755,27.232 32.882,27.105 32.882,25.581 33.136,25.327 34.152,25.327 34.406,25.581 34.406,26.969 33.406,27.969 30.647,27.969 30.162,28.453 30.162,28.806 29.946,29.023
PGND on Top Layer "TOP_LAYER_PGND_P537" (solid, pour order 537): 3.86,3.114 10.969,3.114 10.969,0.117 10.852,0 3.869,0
SW on Top Layer "TOP_LAYER_SW_P536" (solid, pour order 536): 16.912,3.171 19.677,3.171 19.692,3.155 20.32,2.527 20.32,0.793 19.527,0 13.34,0 13.34,6.561 14.831,8.051 14.831,13.75 16.706,15.625 19.344,15.625 19.527,15.442 19.527,13.892 19.392,13.757 16.856,13.757 16.32,13.222 16.32,3.762
SW on Top Layer "TOP_LAYER_SW_P535" (solid, pour order 535): 18.475,18.05 18.958,17.567 23.541,17.567 25.672,19.699 28.069,19.699 28.278,19.908 28.278,21.521 27.649,22.15 19.211,22.15 18.475,21.414
PGND on Top Layer "TOP_LAYER_PGND_P524" (solid, pour order 524): 18.152,10.182 18.589,9.745 28.812,9.745 29.446,10.379 29.445,10.379 29.445,12.049 18.306,12.049 18.152,11.895
NetC9_1 on Top Layer "TOP_LAYER_NETC9_1_P497" (solid, pour order 497): 5.316,11.624 8.427,11.624 8.476,11.575 8.476,10.175 7.524,10.175 6.376,9.026 6.376,8.407 5.326,8.407 5.184,8.549 5.184,11.492
NetC10_2 on Top Layer "TOP_LAYER_NETC10_2_P496" (solid, pour order 496): 8.476,12.498 8.476,13.898 8.375,13.999 5.811,13.999 3.621,11.809 3.621,7.68 3.946,7.356 6.346,7.356 6.376,7.386 6.376,7.905 6.325,7.956 5.013,7.956 4.586,8.382 4.586,11.486 5.598,12.498 7.376,12.498
NetD2_2 on Top Layer "TOP_LAYER_NETD2_2_P494" (solid, pour order 494): 1.8,15.169 2.712,16.082 4.352,16.082 4.586,15.847 4.586,13.527 3.152,12.093 3.152,10.601 2.917,10.366 2.002,10.366 1.8,10.568
NC1 on Top Layer "Top Layer-No Net 2" (solid, remove dead copper, pour order 436): 3.75,37.7 4.7,38.65 12.935,38.65 13.75,37.835 13.75,33.51 13.39,33.15 4.417,33.15 3.75,33.817
NetT1_4 on Top Layer "TOP_LAYER_NETT1_4_P493" (solid, pour order 493): 6.197,26.828 6.146,26.777 6.146,25.861 7.554,24.454 7.554,23.802 8.519,23.802 8.519,25.004 6.695,26.828
HVBUS on Top Layer "MidLayer4-PGND" (solid, pour order 472): 18.152,7.859 18.475,8.182 30.324,8.182 30.764,7.742 30.764,0 24.381,0 18.152,6.229
SW on Top Layer "Top Layer-SW" (solid, pour order 392): 30.342,16.23 30.342,14.28 30.061,13.999 25.868,13.999 25.44,14.427 25.44,16.183 25.495,16.23
PGND on Top Layer "Top Layer-No Net 3" (solid, pour order 438): 16.626,30.434 15.245,31.815 15.245,35.509 15.768,36.033 17.238,36.033 23.917,36.033 24.9,35.05 24.9,25.816 23.95,24.865 17.208,24.865 16.626,25.447
SW on Top Layer "Top Layer-No Net" (solid, pour order 432): 32.958,14.71 33.72,14.71 34.228,14.202 34.228,12.932 34.304,12.856 35.142,12.856 35.625,13.338 37.276,13.338 37.327,13.288 37.327,12.78 37.2,12.653 36.006,12.653 34.057,10.703 32.955,10.703 32.882,10.776 32.882,11.357 33.034,11.51 33.72,11.51 33.974,11.764 33.974,12.576 33.898,12.653 32.983,12.653 32.806,12.83 32.806,14.558
DGND on MidLayer4 "MidLayer4-DGND" (solid, pour order 506): 15.538,35.326 10.208,29.995 10.22,26.37 7.653,23.803 3.132,23.803 0.56,26.336 0.56,38.61 1.65,39.7 49.2,39.7 50,38.9 50,0.5 40.4,0.5 40.4,32.053 37.126,35.326
PGND on MidLayer4 "MidLayer4-PGND 1" (solid, pour order 544): 11.995,0.384 11.995,12.974 15.18,16.158 19.874,16.158 20.379,15.653 20.379,11.157 21.004,10.532 26.05,10.532 26.595,11.077 26.595,25.01 26.595,32.38 25.138,33.838 16.288,33.838 11.995,29.545 11.995,25.558 8.687,22.25 2.35,22.25 0.56,20.46 0.56,5.761 1.321,5 3.229,5 3.66,4.569 3.66,0.405 4.202,0 11.611,0
SW on MidLayer4 "MidLayer1-SW" (solid, pour order 534): 29.353,18.554 29.268,18.639 29.268,21.012 30.406,22.15 36.288,22.15 36.844,21.593 37.454,20.984 37.454,11.342 36.326,10.214 28.411,10.214 27.421,11.205 27.421,16.547
SW on MidLayer4 "MIDLAYER4_SW_P531" (solid, pour order 531): 19.431,16.798 25.003,16.798 25.003,19.001 25.682,19.679 27.845,19.679 28.31,20.144 28.31,21.637 27.951,21.995 19.782,21.995 19.377,21.591
SW on MidLayer4 "MIDLAYER4_SW_P525" (solid, pour order 525): 12.987,0.245 12.987,12.224 16.438,15.675 19.373,15.675 19.672,15.376 19.672,3.36 20.379,2.653 20.379,0
HVBUS on MidLayer4 "MidLayer4-PGND" (solid, pour order 471): 20.346,7.925 20.603,8.182 30.324,8.182 30.743,7.763 30.743,0 24.41,0 20.346,4.064
PGND on MidLayer4 "MidLayer1-PGND" (solid, pour order 400): 36.43,23.55 37.428,24.548 37.428,32.087 35.865,33.65 28.675,33.65 27.421,32.396 27.421,25.099 28.97,23.55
